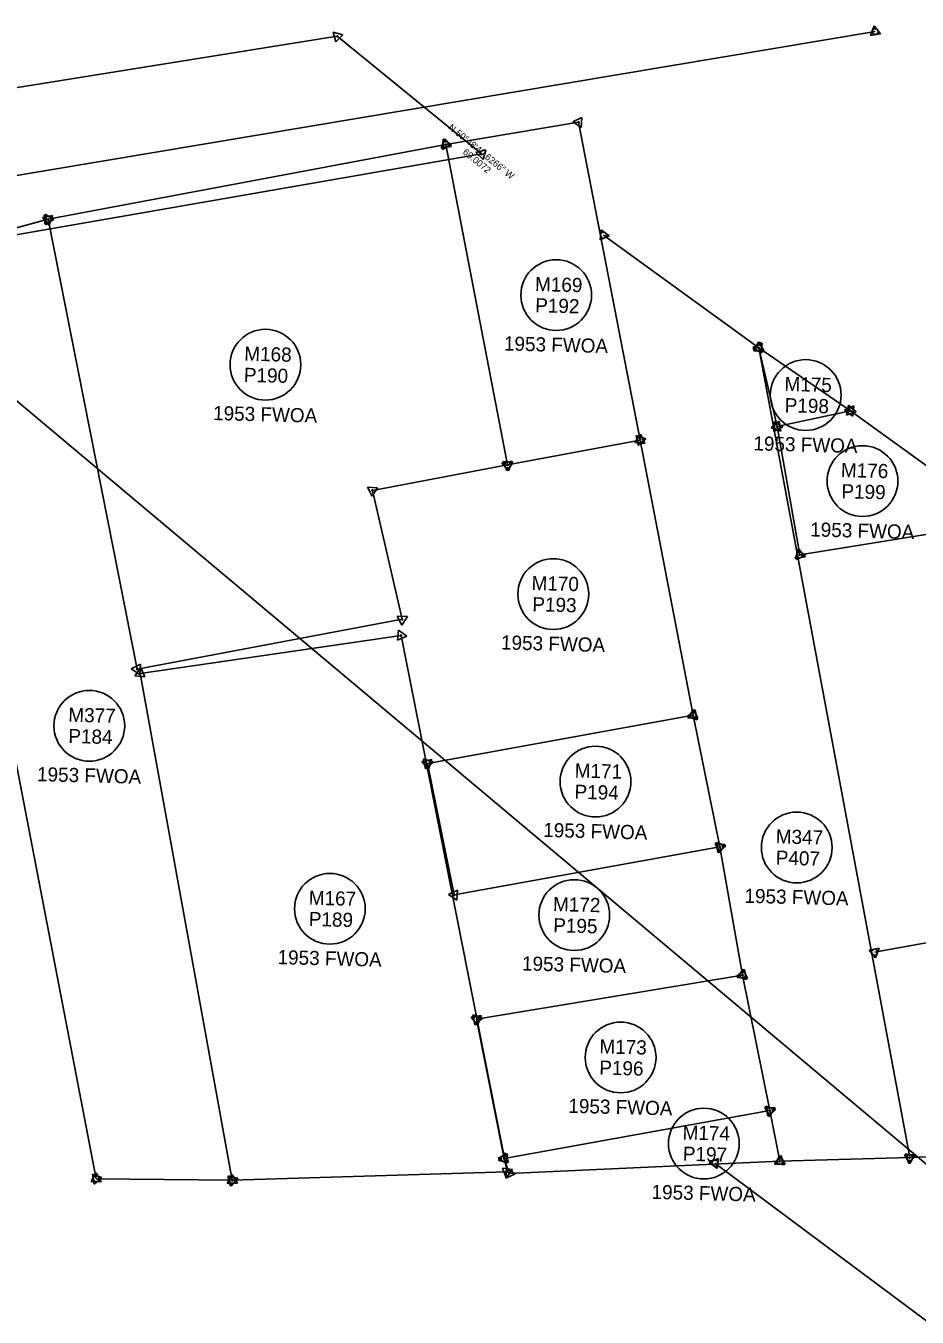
# Model space of a CAD drawing. Extents: x 325018 to 414989, y 1517547 to 1550415.
# Drawn here: x 363895.4 to 364226, y 1523754 to 1524232.9 of the extents above; entities that cross this region are included whole.
import ezdxf

# ---------------------------------------------------------------- set-up
doc = ezdxf.new("R2010")
doc.units = 0
for name, color, linetype in [('ADEFAULT', 7, 'Continuous'), ('Level 56', 7, 'Continuous'), ('MEE', 7, 'Continuous'), ('MHBWOA', 7, 'Continuous'), ('MRBL1', 7, 'Continuous'), ('MRBL2', 7, 'Continuous'), ('XDEFAULT_P', 7, 'Continuous'), ('XDEFAULT_P_T', 7, 'Continuous')]:
    doc.layers.add(name, color=color, linetype=linetype)

msp = doc.modelspace()

# ---------------------------------------------------------------- linework, layer by layer
at = {"layer": 'ADEFAULT'}
for points in [[(364010.38, 1524226.93), (364009.4, 1524230.58)], [(364009.4, 1524230.58), (364013.05, 1524229.6)], [(364013.05, 1524229.6), (364010.38, 1524226.93)], [(364062.32, 1524185.98), (364065.96, 1524186.98)], [(364065.01, 1524183.33), (364062.32, 1524185.98)], [(364065.96, 1524186.98), (364065.01, 1524183.33)]]:
    msp.add_lwpolyline(points, dxfattribs=at)
for centre in [(364010.94, 1524229.04), (364064.43, 1524185.43)]:
    msp.add_circle(centre, 0.227, dxfattribs=at)
at = {"layer": 'Level 56'}
for centre in [(364092.12, 1524133.05), (363984.27, 1524107.24), (364184.64, 1524095.99), (364205.7, 1524064.07), (364091.04, 1524022.16), (363918.97, 1523973.3), (364106.7, 1523952.62), (364181.33, 1523928.18), (364008.18, 1523905.44), (364098.82, 1523903.1), (364116.01, 1523850.3), (364146.87, 1523818.37)]:
    msp.add_circle(centre, 13.12, dxfattribs=at)
at = {"layer": 'MEE'}
msp.add_line((364151, 1523811.11), (364334.73, 1523673.81), dxfattribs=at)
for points in [[(364148.83, 1523811.37), (364152.3, 1523812.86)], [(364151.85, 1523809.11), (364148.83, 1523811.37)], [(364152.3, 1523812.86), (364151.85, 1523809.11)]]:
    msp.add_lwpolyline(points, dxfattribs=at)
msp.add_circle((364151, 1523811.11), 1.09, dxfattribs=at)
at = {"layer": 'MHBWOA'}
for p, q in [((364010.94, 1524229.04), (363659.53, 1524172.86)), ((364064.43, 1524185.43), (364010.94, 1524229.04)), ((364051.13, 1524188.89), (364100.44, 1524197.15)), ((364100.44, 1524197.15), (364123.22, 1524079.3)), ((363721.83, 1524125.76), (364064.43, 1524185.43)), ((364051.13, 1524188.89), (363903.69, 1524161.16)), ((364074.07, 1524070.05), (364051.13, 1524188.89)), ((363903.69, 1524161.16), (363855.46, 1524148.06)), ((363903.69, 1524161.16), (363936.7, 1523994.32)), ((364167.23, 1524113.48), (364109.64, 1524155.3)), ((363855.46, 1524148.06), (363921.53, 1523805.31)), ((364167.23, 1524113.48), (364201.2, 1524090.18)), ((364174.04, 1524084.26), (364167.23, 1524113.48)), ((364223.22, 1523813.15), (364167.23, 1524113.48)), ((364201.2, 1524090.18), (364174.04, 1524084.26)), ((364201.2, 1524090.18), (364258.03, 1524048.99)), ((364182.44, 1524036.73), (364174.04, 1524084.26)), ((364123.22, 1524079.3), (364074.07, 1524070.05)), ((364123.22, 1524079.3), (364142.91, 1523977.21)), ((364023.94, 1524060.64), (364074.07, 1524070.05)), ((364034.99, 1524012.81), (364023.94, 1524060.64)), ((364182.44, 1524036.73), (364258.03, 1524048.99)), ((363936.7, 1523994.32), (364034.99, 1524012.81)), ((364034.57, 1524006.8), (363937.85, 1523992.7)), ((364073.91, 1523807.94), (364034.57, 1524006.8)), ((363937.85, 1523992.7), (363971.98, 1523804.74)), ((364142.91, 1523977.21), (364044.38, 1523959.39)), ((364152.84, 1523928.39), (364142.91, 1523977.21)), ((364044.38, 1523959.39), (364054.31, 1523910.57)), ((364054.31, 1523910.57), (364152.84, 1523928.39)), ((364152.84, 1523928.39), (364161.24, 1523880.85)), ((364407.24, 1523925.01), (364210.19, 1523889.38)), ((364161.24, 1523880.85), (364062.59, 1523864.45)), ((364171.3, 1523830.63), (364161.24, 1523880.85)), ((364062.59, 1523864.45), (364072.77, 1523812.81)), ((364072.77, 1523812.81), (364171.3, 1523830.63)), ((364171.3, 1523830.63), (364175.07, 1523811.79)), ((364426.95, 1523820.97), (364223.22, 1523813.15)), ((364074.67, 1523807.3), (364072.77, 1523812.81)), ((364175.07, 1523811.79), (364074.67, 1523807.3)), ((364175.07, 1523811.79), (364223.22, 1523813.15)), ((363971.98, 1523804.74), (364073.91, 1523807.94)), ((363921.53, 1523805.31), (363971.98, 1523804.74))]:
    msp.add_line(p, q, dxfattribs=at)
for points in [[(364098.27, 1524197.33), (364101.68, 1524198.94)], [(364101.68, 1524198.94), (364101.37, 1524195.18)], [(364101.37, 1524195.18), (364098.27, 1524197.33)], [(364049.45, 1524187.5), (364050.77, 1524191.04)], [(364049.91, 1524187.09), (364050.18, 1524190.86)], [(364050.18, 1524190.86), (364053.31, 1524188.74)], [(364050.77, 1524191.04), (364053.17, 1524188.13)], [(364053.17, 1524188.13), (364049.45, 1524187.5)], [(364053.31, 1524188.74), (364049.91, 1524187.09)], [(363901.63, 1524161.89), (363905.34, 1524162.58)], [(363904.09, 1524159.02), (363901.63, 1524161.89)], [(363902.25, 1524162.8), (363905.82, 1524161.58)], [(363902.98, 1524159.09), (363902.25, 1524162.8)], [(363902.53, 1524159.31), (363902.66, 1524163.09)], [(363905.87, 1524161.09), (363902.53, 1524159.31)], [(363902.66, 1524163.09), (363905.87, 1524161.09)], [(363905.82, 1524161.58), (363902.98, 1524159.09)], [(363905.34, 1524162.58), (363904.09, 1524159.02)], [(364108.36, 1524153.54), (364108.76, 1524157.3)], [(364108.76, 1524157.3), (364111.81, 1524155.08)], [(364111.81, 1524155.08), (364108.36, 1524153.54)], [(364165.05, 1524113.64), (364168.46, 1524115.27)], [(364168.17, 1524111.51), (364165.05, 1524113.64)], [(364165.11, 1524112.98), (364167.87, 1524115.57)], [(364168.72, 1524111.89), (364165.11, 1524112.98)], [(364165.39, 1524112.31), (364167.15, 1524115.66)], [(364169.16, 1524112.46), (364165.39, 1524112.31)], [(364167.15, 1524115.66), (364169.16, 1524112.46)], [(364167.87, 1524115.57), (364168.72, 1524111.89)], [(364168.46, 1524115.27), (364168.17, 1524111.51)], [(364199.03, 1524090.4), (364202.48, 1524091.94)], [(364202.09, 1524088.18), (364199.03, 1524090.4)], [(364199.77, 1524088.53), (364200.49, 1524092.24)], [(364203.34, 1524089.76), (364199.77, 1524088.53)], [(364200.49, 1524092.24), (364203.34, 1524089.76)], [(364202.48, 1524091.94), (364202.09, 1524088.18)], [(364171.89, 1524083.88), (364174.78, 1524086.31)], [(364175.44, 1524082.59), (364171.89, 1524083.88)], [(364172.87, 1524082.42), (364173.02, 1524086.19)], [(364176.22, 1524084.17), (364172.87, 1524082.42)], [(364173.02, 1524086.19), (364176.22, 1524084.17)], [(364174.78, 1524086.31), (364175.44, 1524082.59)], [(364121.26, 1524078.35), (364123.38, 1524081.47)], [(364121.79, 1524080.94), (364125.36, 1524079.71)], [(364122.51, 1524077.23), (364121.79, 1524080.94)], [(364125.36, 1524079.71), (364122.51, 1524077.23)], [(364123.38, 1524081.47), (364125.02, 1524078.07)], [(364125.02, 1524078.07), (364121.26, 1524078.35)], [(364072.01, 1524070.78), (364075.73, 1524071.48)], [(364074.48, 1524067.91), (364072.01, 1524070.78)], [(364073.92, 1524067.87), (364072.27, 1524071.28)], [(364072.27, 1524071.28), (364076.04, 1524071)], [(364076.04, 1524071), (364073.92, 1524067.87)], [(364075.73, 1524071.48), (364074.48, 1524067.91)], [(364023.82, 1524058.46), (364022.12, 1524061.83)], [(364022.12, 1524061.83), (364025.89, 1524061.62)], [(364025.89, 1524061.62), (364023.82, 1524058.46)], [(364180.75, 1524035.34), (364182.09, 1524038.88)], [(364184.48, 1524035.95), (364180.75, 1524035.34)], [(364181.18, 1524034.95), (364181.53, 1524038.71)], [(364184.61, 1524036.52), (364181.18, 1524034.95)], [(364181.53, 1524038.71), (364184.61, 1524036.52)], [(364182.09, 1524038.88), (364184.48, 1524035.95)], [(364034.87, 1524010.63), (364033.17, 1524014)], [(364033.17, 1524014), (364036.94, 1524013.79)], [(364036.94, 1524013.79), (364034.87, 1524010.63)], [(364033.31, 1524005.03), (364033.66, 1524008.79)], [(364033.66, 1524008.79), (364036.74, 1524006.61)], [(364036.74, 1524006.61), (364033.31, 1524005.03)], [(363934.52, 1523994.47), (363937.92, 1523996.13)], [(363937.65, 1523992.36), (363934.52, 1523994.47)], [(363935.86, 1523991.8), (363938.06, 1523994.87)], [(363937.92, 1523996.13), (363937.65, 1523992.36)], [(363938.06, 1523994.87), (363939.62, 1523991.43)], [(363939.62, 1523991.43), (363935.86, 1523991.8)], [(364140.77, 1523976.77), (364143.6, 1523979.28)], [(364140.94, 1523976.27), (364143.07, 1523979.38)], [(364143.07, 1523979.38), (364144.7, 1523975.98)], [(364143.6, 1523979.28), (364144.36, 1523975.57)], [(364144.36, 1523975.57), (364140.77, 1523976.77)], [(364144.7, 1523975.98), (364140.94, 1523976.27)], [(364042.33, 1523960.13), (364046.05, 1523960.81)], [(364044.77, 1523957.25), (364042.33, 1523960.13)], [(364042.93, 1523961.03), (364046.51, 1523959.83)], [(364043.69, 1523957.32), (364042.93, 1523961.03)], [(364046.51, 1523959.83), (364043.69, 1523957.32)], [(364046.05, 1523960.81), (364044.77, 1523957.25)], [(364152.69, 1523926.21), (364151.04, 1523929.61)], [(364151.04, 1523929.61), (364154.81, 1523929.34)], [(364151.44, 1523930.06), (364154.99, 1523928.77)], [(364152.09, 1523926.34), (364151.44, 1523930.06)], [(364154.99, 1523928.77), (364152.09, 1523926.34)], [(364154.81, 1523929.34), (364152.69, 1523926.21)], [(364052.14, 1523910.73), (364055.54, 1523912.38)], [(364055.54, 1523912.38), (364055.26, 1523908.61)], [(364055.26, 1523908.61), (364052.14, 1523910.73)], [(364208.13, 1523890.12), (364211.85, 1523890.79)], [(364210.57, 1523887.24), (364208.13, 1523890.12)], [(364211.85, 1523890.79), (364210.57, 1523887.24)], [(364159.11, 1523880.43), (364161.94, 1523882.92)], [(364159.26, 1523879.94), (364161.44, 1523883.03)], [(364161.44, 1523883.03), (364163.02, 1523879.6)], [(364161.94, 1523882.92), (364162.69, 1523879.22)], [(364162.69, 1523879.22), (364159.11, 1523880.43)], [(364163.02, 1523879.6), (364159.26, 1523879.94)], [(364060.55, 1523865.22), (364064.28, 1523865.84)], [(364062.95, 1523862.3), (364060.55, 1523865.22)], [(364061.15, 1523866.09), (364064.73, 1523864.87)], [(364061.88, 1523862.38), (364061.15, 1523866.09)], [(364064.73, 1523864.87), (364061.88, 1523862.38)], [(364064.28, 1523865.84), (364062.95, 1523862.3)], [(364171.14, 1523828.45), (364169.5, 1523831.85)], [(364169.5, 1523831.85), (364173.27, 1523831.57)], [(364169.86, 1523832.26), (364173.43, 1523831.05)], [(364170.6, 1523828.56), (364169.86, 1523832.26)], [(364173.43, 1523831.05), (364170.6, 1523828.56)], [(364173.27, 1523831.57), (364171.14, 1523828.45)], [(364070.59, 1523812.97), (364074, 1523814.61)], [(364073.72, 1523810.84), (364070.59, 1523812.97)], [(364070.71, 1523812.1), (364073.19, 1523814.96)], [(364074.42, 1523811.38), (364070.71, 1523812.1)], [(364073.19, 1523814.96), (364074.42, 1523811.38)], [(364074, 1523814.61), (364073.72, 1523810.84)], [(364173.04, 1523810.98), (364175.37, 1523813.95)], [(364176.78, 1523810.45), (364173.04, 1523810.98)], [(364173.21, 1523810.64), (364175.01, 1523813.97)], [(364176.99, 1523810.75), (364173.21, 1523810.64)], [(364175.01, 1523813.97), (364176.99, 1523810.75)], [(364175.37, 1523813.95), (364176.78, 1523810.45)], [(364221.29, 1523814.17), (364225.06, 1523814.31)], [(364223.3, 1523810.97), (364221.29, 1523814.17)], [(364222.88, 1523810.99), (364221.52, 1523814.52)], [(364221.52, 1523814.52), (364225.25, 1523813.93)], [(364225.25, 1523813.93), (364222.88, 1523810.99)], [(364225.06, 1523814.31), (364223.3, 1523810.97)], [(363919.63, 1523804.24), (363921.56, 1523807.49)], [(363920.1, 1523806.96), (363923.67, 1523805.72)], [(363920.81, 1523803.25), (363920.1, 1523806.96)], [(363921.56, 1523807.49), (363923.41, 1523804.19)], [(363970.12, 1523803.58), (363971.91, 1523806.91)], [(363971.6, 1523802.59), (363970.31, 1523806.13)], [(363970.31, 1523806.13), (363974.03, 1523805.49)], [(363970.56, 1523806.4), (363974.12, 1523805.13)], [(363971.24, 1523802.68), (363970.56, 1523806.4)], [(363971.91, 1523806.91), (363973.9, 1523803.7)], [(364073.59, 1523805.78), (364072.2, 1523809.3)], [(364072.2, 1523809.3), (364075.94, 1523808.74)], [(364073.45, 1523805.5), (364073.72, 1523809.27)], [(364076.85, 1523807.14), (364073.45, 1523805.5)], [(364075.94, 1523808.74), (364073.59, 1523805.78)], [(364073.72, 1523809.27), (364076.85, 1523807.14)], [(363923.41, 1523804.19), (363919.63, 1523804.24)], [(363923.67, 1523805.72), (363920.81, 1523803.25)], [(363973.9, 1523803.7), (363970.12, 1523803.58)], [(363974.12, 1523805.13), (363971.24, 1523802.68)], [(363974.03, 1523805.49), (363971.6, 1523802.59)]]:
    msp.add_lwpolyline(points, dxfattribs=at)
for centre, radius in [((364100.44, 1524197.15), 0.227), ((364051.13, 1524188.89), 1.09), ((364051.13, 1524188.89), 0.227), ((363903.69, 1524161.16), 1.09), ((363903.68, 1524161.16), 1.09), ((363903.69, 1524161.16), 0.227), ((364109.64, 1524155.31), 1.09), ((364167.23, 1524113.48), 1.09), ((364167.23, 1524113.48), 1.09), ((364167.23, 1524113.48), 0.227), ((364201.2, 1524090.17), 1.09), ((364201.2, 1524090.18), 0.227), ((364174.04, 1524084.26), 1.09), ((364174.04, 1524084.26), 0.227), ((364123.22, 1524079.29), 1.09), ((364123.22, 1524079.3), 0.227), ((364074.07, 1524070.05), 1.09), ((364074.07, 1524070.05), 0.227), ((364023.94, 1524060.64), 0.227), ((364182.44, 1524036.73), 1.09), ((364182.44, 1524036.73), 0.227), ((364034.99, 1524012.81), 0.227), ((364034.57, 1524006.8), 0.227), ((363936.7, 1523994.32), 0.227), ((363937.85, 1523992.7), 0.227), ((364142.91, 1523977.21), 1.09), ((364142.91, 1523977.21), 0.227), ((364044.38, 1523959.39), 1.09), ((364044.38, 1523959.39), 1.09), ((364152.84, 1523928.39), 1.09), ((364152.84, 1523928.39), 0.227), ((364054.31, 1523910.57), 0.227), ((364210.18, 1523889.38), 1.09), ((364161.24, 1523880.86), 1.09), ((364161.24, 1523880.85), 0.227), ((364062.59, 1523864.45), 1.09), ((364062.59, 1523864.45), 1.09), ((364171.3, 1523830.62), 1.09), ((364171.3, 1523830.63), 0.227), ((364072.77, 1523812.81), 1.09), ((364072.77, 1523812.81), 0.227), ((364175.07, 1523811.79), 1.09), ((364175.07, 1523811.79), 0.227), ((364223.21, 1523813.15), 1.09), ((364223.22, 1523813.15), 0.227), ((363921.53, 1523805.31), 1.09), ((363921.53, 1523805.31), 1.09), ((364073.91, 1523807.94), 0.227), ((364074.67, 1523807.3), 0.227), ((363971.98, 1523804.74), 1.09), ((363971.98, 1523804.74), 1.09), ((363971.98, 1523804.74), 0.227)]:
    msp.add_circle(centre, radius, dxfattribs=at)
at = {"layer": 'MRBL1'}
msp.add_line((363809.01, 1524163.56), (364210.4, 1524230.78), dxfattribs=at)
for points in [[(364208.72, 1524229.39), (364210.04, 1524232.92)], [(364210.04, 1524232.92), (364212.44, 1524230.01)], [(364212.44, 1524230.01), (364208.72, 1524229.39)]]:
    msp.add_lwpolyline(points, dxfattribs=at)
msp.add_circle((364210.4, 1524230.78), 1.09, dxfattribs=at)
at = {"layer": 'MRBL2'}
msp.add_line((363809.01, 1524163.56), (364281.98, 1523766.42), dxfattribs=at)
at = {"layer": 'XDEFAULT_P'}
for p, q in [((364064.43, 1524185.43), (364010.94, 1524229.04)), ((363721.83, 1524125.76), (364064.43, 1524185.43))]:
    msp.add_line(p, q, dxfattribs=at)

# ---------------------------------------------------------------- texts
at = {"layer": 'Level 56'}
for s, p in [('M169', (364084.22, 1524134.57)), ('P192', (364084.28, 1524126.69)), ('1953 FWOA', (364072.67, 1524112.53)), ('M168', (363976.39, 1524108.76)), ('P190', (363976.24, 1524100.88)), ('M175', (364176.71, 1524097.51)), ('P198', (364176.8, 1524089.63)), ('1953 FWOA', (363964.82, 1524086.72)), ('1953 FWOA', (364165.19, 1524075.48)), ('M176', (364197.65, 1524065.59)), ('P199', (364197.84, 1524057.71)), ('1953 FWOA', (364186.25, 1524043.56)), ('M170', (364082.92, 1524023.68)), ('P193', (364083.22, 1524015.8)), ('1953 FWOA', (364071.59, 1524001.64)), ('M377', (363911.13, 1523974.82)), ('P184', (363911.14, 1523966.94)), ('M171', (364098.94, 1523954.13)), ('1953 FWOA', (363899.53, 1523952.79)), ('P194', (364098.86, 1523946.26)), ('1953 FWOA', (364087.25, 1523932.1)), ('M347', (364173.49, 1523929.7)), ('P407', (364173.49, 1523921.82)), ('M167', (364000.3, 1523906.96)), ('1953 FWOA', (364161.88, 1523907.67)), ('M172', (364090.89, 1523904.61)), ('P189', (364000.32, 1523899.08)), ('P195', (364090.98, 1523896.74)), ('1953 FWOA', (363988.73, 1523884.93)), ('1953 FWOA', (364079.37, 1523882.58)), ('M173', (364108.09, 1523851.82)), ('P196', (364108.04, 1523843.94)), ('1953 FWOA', (364096.56, 1523829.78)), ('M174', (364138.94, 1523819.89)), ('P197', (364139.03, 1523812.01)), ('1953 FWOA', (364127.42, 1523797.85))]:
    msp.add_text(s, height=5.249, rotation=358.5141, dxfattribs=at).set_placement(p)
at = {"layer": 'XDEFAULT_P_T'}
for s, height, p in [('N 50%%d48\'40.6266" W', 2.5008, (364051.9, 1524194.84)), ('69.0072', 2.501, (364057.23, 1524185.65))]:
    msp.add_text(s, height=height, rotation=320.8113, dxfattribs=at).set_placement(p)

doc.saveas('drawing.dxf')
